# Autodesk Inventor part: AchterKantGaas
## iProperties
Created: 2010-03
Part Number: AchterKantGaas
Document SubType Name: Modeling
Designer: Ferry
Density: 1 g/cm^3
Author: Ferry
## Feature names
1. Extrusion1
